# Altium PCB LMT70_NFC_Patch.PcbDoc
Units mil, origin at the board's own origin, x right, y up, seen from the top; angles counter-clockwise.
Board outline 1256 x 1256 mil, 2 copper layers (Top Layer, Bottom Layer); 28 components, 19 nets, 113 pads, 34 vias.
Unrouted connection lines stored in the file: 2.
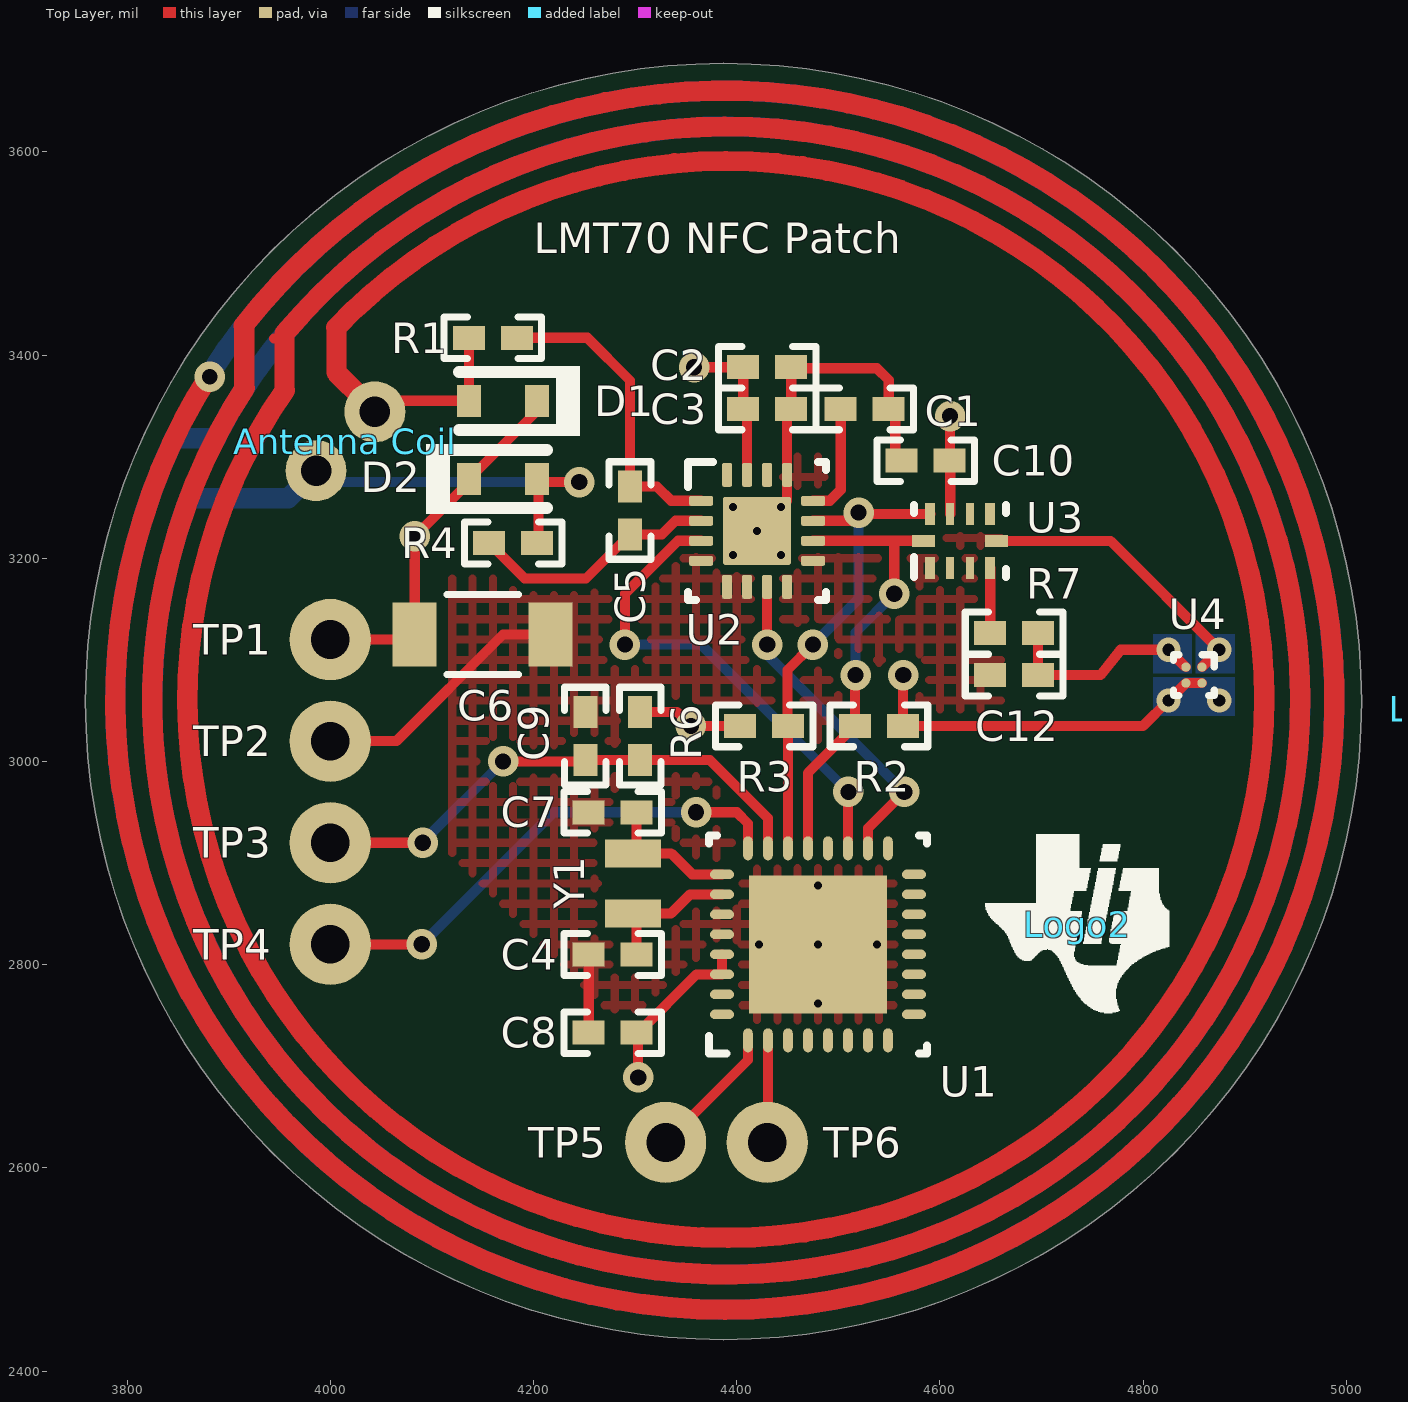
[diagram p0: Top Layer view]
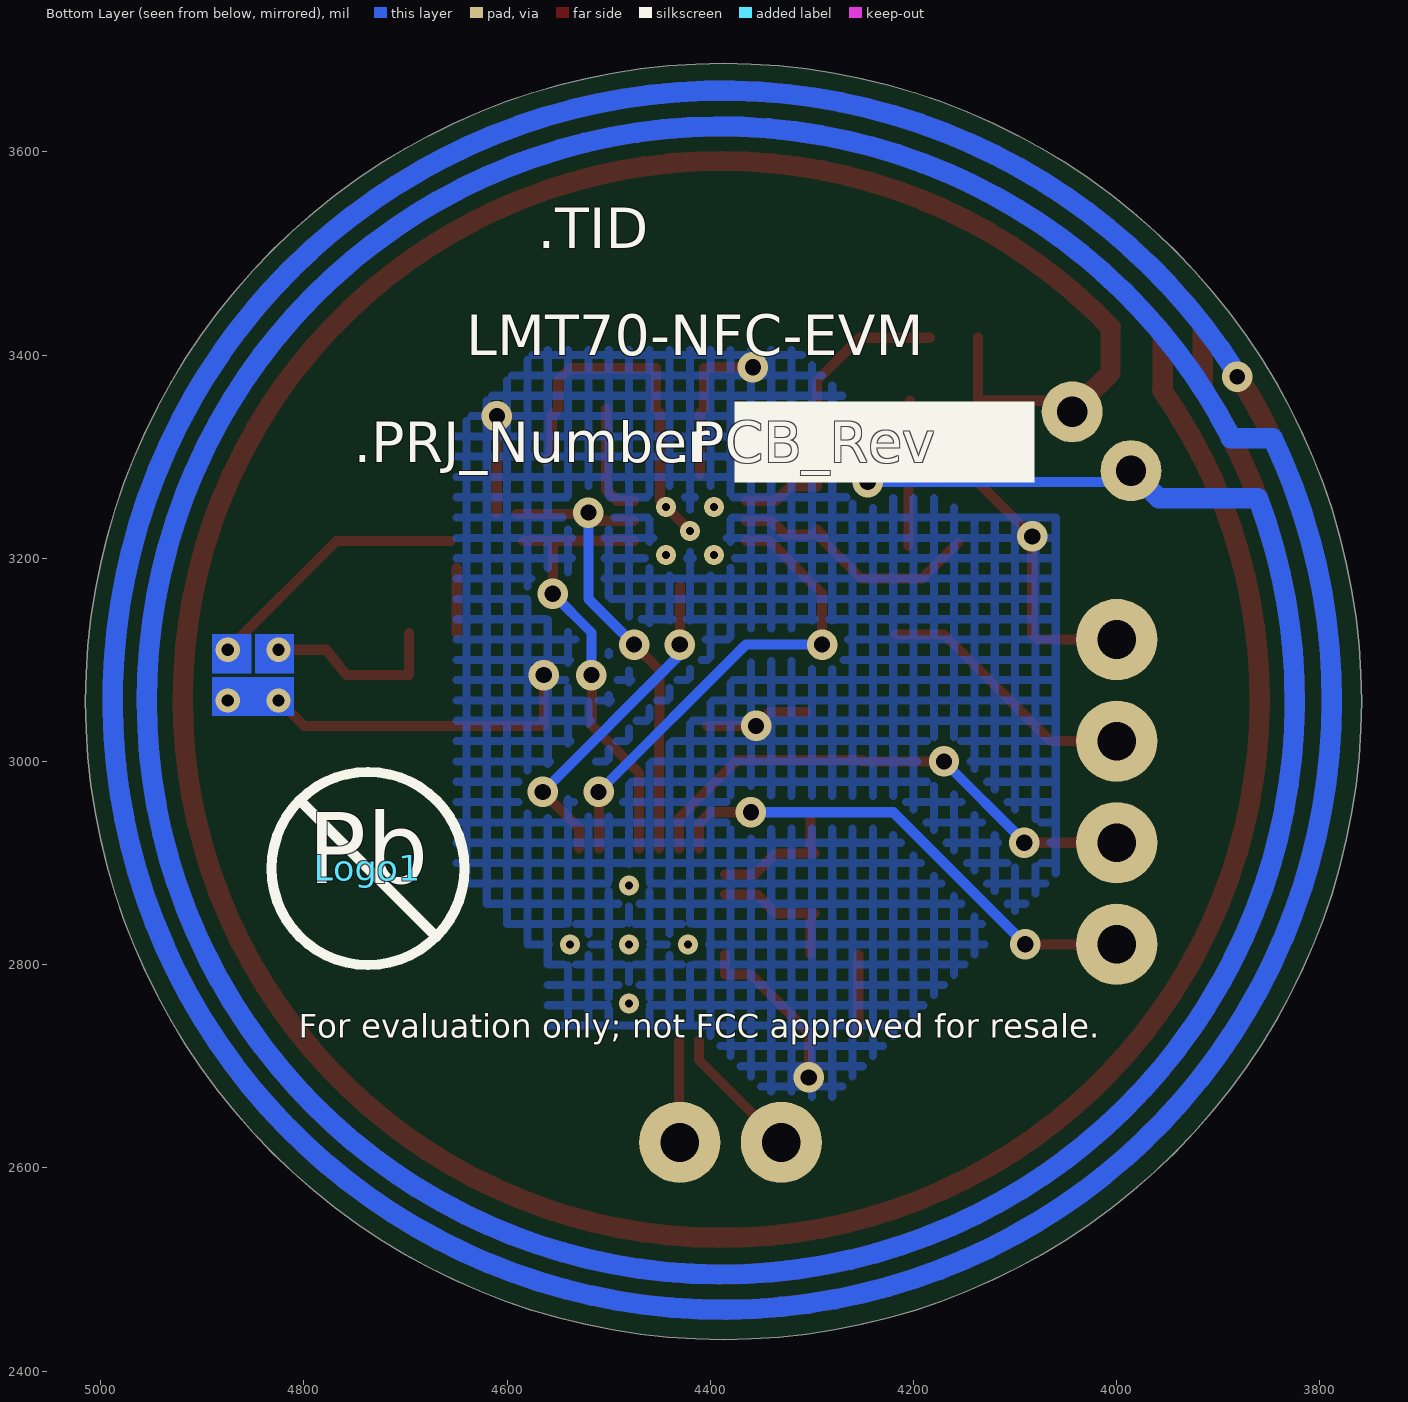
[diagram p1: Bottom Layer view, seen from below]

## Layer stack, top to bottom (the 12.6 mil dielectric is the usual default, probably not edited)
Top Solder: solder mask 0.4, Solder Resist, Dk 3.5
Top Layer: signal copper 1.4
Dielectric1: dielectric 12.6, FR-4, Dk 4.8
Bottom Layer: signal copper 1.4
Bottom Solder: solder mask 0.4, Solder Resist, Dk 3.5

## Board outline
3759.02,3059 ccw(c4387.02,3059) 4387.02,2431 ccw(c4387.02,3059) 5015.02,3059 ccw(c4387.02,3059) 4387.02,3687 ccw(c4387.02,3059)

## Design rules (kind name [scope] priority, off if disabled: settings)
AcuteAngle [All] p1: minimum=4.50000000000000E+0001 checktracksonly=FALSE
AssemblyTestPointUsage [All] p1: valid=2
Clearance Clearance_BoardEdge_MountingHoles [OnCopper and InComponentClass('Mounting Holes') vs IsKeepOut] p1: gap=20
Clearance Clearance_BoardEdge_Poly [OnCopper and InPoly vs IsKeepOut] p2: gap=20
Clearance Clearance_BoardEdge [OnCopper and Not InComponentClass('Logo') and not InComponentClass('FiducialMark') and not InRegion(1000,500,4000,800) vs IsKeepOut] p3: gap=20
Clearance Clearance_Poly [InPolygon] p4: gap=7
Clearance [All] p5: gap=3
ComponentClearance ComponentClearance_Shunt [InComponentClass('Header') vs InComponentClass('Shunt')] p1 off: gap=0 collisioncheckmode=3 verticalgap=0 showdistances=FALSE
ComponentClearance ComponentClearance_Logo [InComponentClass(Logo)] p2 off: gap=50 collisioncheckmode=3 verticalgap=10 showdistances=FALSE
ComponentClearance ComponentClearance_ScrewToNut [(HasFootprint('NY PMS 440 0025 PH')) vs (HasFootprint('Keystone_1902C'))] p3 off: gap=5 collisioncheckmode=3 verticalgap=10 showdistances=FALSE
ComponentClearance ComponentClearance_MountingHoles [InComponentClass('Mounting Holes')] p4 off: gap=250 collisioncheckmode=3 verticalgap=100000 showdistances=FALSE
ComponentClearance ComponentClearance_SmallPassives [HasFootprint('0201*') or HasFootprint('0402*') or HasFootprint('0508') or HasFootprint('0603*') or HasFootprint('0612') or HasFootprint('0805*') or HasFootprint('0815*') or HasFootprint('0830*') or HasFootprint('1206*') or HasFootprint('1210*') or HasFootprint('1808*') or HasFootprint('1812*') or HasFootprint('1825*') or HasFootprint('2010*') or HasFootprint('2220*') or HasFootprint('2225*') or HasFootprint('2512*') or HasFootprint('2728*') or HasFootprint('3518*') vs HasFootprint('0201*') or HasFootprint('0402*') or HasFootprint('0508') or HasFootprint('0603*') or HasFootprint('0612') or HasFootprint('0805*') or HasFootprint('0815*') or HasFootprint('0830*') or HasFootprint('1206*') or HasFootprint('1210*') or HasFootprint('1808*') or HasFootprint('1812*') or HasFootprint('1825*') or HasFootprint('2010*') or HasFootprint('2220*') or HasFootprint('2225*') or HasFootprint('2512*') or HasFootprint('2728*') or HasFootprint('3518*')] p5 off: gap=20 collisioncheckmode=3 verticalgap=10 showdistances=FALSE
ComponentClearance ComponentClearance_THtoSMT [IsThruComponent vs IsSMTComponent] p6 off: gap=100 collisioncheckmode=3 verticalgap=100000 showdistances=FALSE
ComponentClearance ComponentClearance_THtoTH [IsThruComponent vs IsThruComponent] p7 off: gap=118.11 collisioncheckmode=3 verticalgap=100000 showdistances=FALSE
ComponentClearance [All] p8 off: gap=4 collisioncheckmode=3 verticalgap=10 showdistances=FALSE
DiffPairsRouting [All] p1: maxlimit=100 minlimit=10 mostfreqgap=10 toplayer_minwidth=15 toplayer_maxwidth=15 toplayer_prefwidth=15 bottomlayer_minwidth=15 bottomlayer_maxwidth=15 bottomlayer_prefwidth=15 maxuncoupledlength=1000
FabricationTestPointUsage TestPointUsage [All] p1: valid=2 allowmultiple=FALSE
FabricationTestpoint Testpoint [All] p1: side=3 testpointundercomponent=TRUE minsize=40 maxsize=100 preferedsize=60 minholesize=0 maxholesize=40 preferedholesize=32 testpointgrid=1 allowsidetop=TRUE allowsidebottom=TRUE usegrid=TRUE gridtolerance=0.01
FanoutControl Fanout_LCC [IsLCC] p1: bgadir=Out bgaviamode=Centered fanoutstyle=Auto fanoutdirection=Alternating viagrid=1 // Fanout_LCC (Default Rule)
FanoutControl Fanout_BGA [IsBGA] p2: bgadir=Out bgaviamode=Centered fanoutstyle=Auto fanoutdirection=Alternating viagrid=1 // Fanout_BGA (Default Rule)
FanoutControl Fanout_Default [All] p4: bgadir=Out bgaviamode=Centered fanoutstyle=Auto fanoutdirection=Alternating viagrid=1 // Fanout_Default (Default Rule)
FanoutControl Fanout_Small [(CompPinCount < 5)] p5: bgadir=Out bgaviamode=Centered fanoutstyle=Auto fanoutdirection=OutThenIn viagrid=1 // Fanout_Small (Default Rule)
HoleSize [All] p1: absolutevalues=TRUE maxlimit=550 minlimit=5 maxpercent=80.000 minpercent=20.000
HoleToHoleClearance [All] p1: gap=3 allowstackedmicrovias=TRUE
MinimumAnnularRing MinimumAnnularRing_ThermalPadVias [IsVia and InAnyComponent] p1: minimumring=5.91
MinimumAnnularRing [All] p2: minimumring=5
MinimumSolderMaskSliver MinimumSolderMaskSliver_Logo [InComponentClass('Logo') vs InComponentClass('Logo')] p1: minsoldermaskwidth=0.7
MinimumSolderMaskSliver [All] p2: minsoldermaskwidth=3
NetAntennae [All] p1 off: netantennaetolerance=0
PlaneConnect [All] p1: planeconnectstyle=Relief reliefexpansion=10 reliefentries=4 reliefconductorwidth=10 reliefairgap=10
PolygonConnect [All] p1: connectstyle=Direct reliefconductorwidth=10 reliefentries=4 polygonreliefangle="90 Angle" airgapwidth=10
RoutingVias ThermalPadVias [IsVia and InAnyComponent] p1: holewidth=7.87 width=19.68 viastyle="Through Hole" minholewidth=7.87 minwidth=19.68 maxholewidth=15 maxwidth=30
RoutingVias [All] p2: holewidth=12 width=28 viastyle="Through Hole" minholewidth=5 minwidth=20 maxholewidth=100 maxwidth=150
SilkToSilkClearance [All] p1: silktosilkclearance=2
SilkToSolderMaskClearance SilkscreenOverComponentPads [IsPad] p1: minsilkscreentomaskgap=2.6 clearancetoexposedcopper=TRUE
SolderMaskExpansion [All] p1: expansion=3
UnpouredPolygon [All] p1: allowunpoured=FALSE
Width [All] p1: maxlimit=100 minlimit=6 preferedwidth=10 checkconnectedcopper=TRUE
13 further rules are at their usual default settings.

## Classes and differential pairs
component class Logo: Logo2

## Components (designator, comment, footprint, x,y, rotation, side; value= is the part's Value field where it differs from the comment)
"Antenna Coil" "Antenna Coil" PCBComponent_1 4389,3060 r315 top locked
C1 "GRM155R61C474KE01" 0402 4526,3347 r0 top
C2 "GRM155R61E105KA12D" 0402 4430,3388 r0 top
C3 "GRM155R61E104KA87D" 0402 4430,3347 r0 top
C4 "GRM1555C1E120JA01D" 0402 4278,2810 r0 top
C5 "GRM1555C1E390JA01D" 0402 4295,3247 r270 top
C6 "C3216X5R1A107M160AC" 1206_190 4150,3125 r0 top
C7 "GRM1555C1E120JA01D" 0402 4278,2950 r0 top
C8 "GRM155R61E104KA87D" 0402 4278,2733 r180 top
C9 "GRM155R71C222KA01D" 0402 4251,3025 r90 top
C10 "GRM155R61E104KA87D" 0402 4586,3296 r180 top
C12 "GRM155R61E102KA01D" 0402 4673,3085 r180 top
D1 "CDBU0130L" SOD-523F 4170,3355 r180 top
D2 "CDBU0130L" SOD-523F 4170,3278 r0 top
Logo1 "Pb-Free Symbol" Pb-Free_Overlay_Medium 4736.94,2894.7 r180 bottom
Logo2 "Texas Instruments" TI_Symbol_Overlay_Small 4735,2840 r0 top
Logo3 "FCC disclaimer" FCC_disclaimer 5095,3052 r90 top
R1 "CRCW04020000Z0ED" 0402 4160,3417 r180 top
R2 "CRCW04024K70JNED" 0402 4540,3035 r0 top
R3 "CRCW04024K70JNED" 0402 4427,3035 r180 top
R4 "CRCW04020000Z0ED" 0402 4180,3215 r0 top
R6 "CRCW040233K0JNED" 0402 4305,3025 r90 top
R7 "CRCW04020000Z0ED" 0402 4673,3126.42 r0 top
U1 "MSP430G2403IRHB32R" RHB0032E 4480,2820 r90 top
U2 "RF430CL330HIRGTR" RGT0016C 4420,3227 r0 top
U3 "ADS1113IRUGR" RUG0010A 4620,3217 r90 top
U4 "LMT70YFQR" YFQ0004ACAC 4850,3085 r270 top
Y1 "FC-12M 32.7680KA-A3" Epson_FC-12M 4297.76,2880 r270 top

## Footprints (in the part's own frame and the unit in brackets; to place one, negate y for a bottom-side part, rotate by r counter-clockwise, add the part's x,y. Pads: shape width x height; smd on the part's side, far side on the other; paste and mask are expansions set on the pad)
0402 [mm] "0402 from SM-752 data"
  rect 0.8x0.6 smd: 1(-0.6,0) 2(0.6,0)
  silkscreen extent -1.22,-0.52 1.22,0.52, body extent -0.55,-0.3 0.55,0.3, height 0.6
1206_190 [mm] "1206_190"
  rect 1.1x1.6 smd: 1(-1.7,0) 2(1.7,0)
  silkscreen extent -0.9,-1 0.9,1, body extent -1.75,-0.95 1.75,0.95, height 1.9
Epson_FC-12M [mm] "Epson"
  rect 0.7x1.4 smd: 1(-0.75,0) 2(0.75,0)
  body extent -1.05,-0.63 1.05,0.63, height 0.6
FCC_disclaimer [mil]
Pb-Free_Overlay_Medium [mil]
  silkscreen extent -95,-95 95,95
PCBComponent_1 [mil]
  round 60 hole 30: 1(-445,-43.17) 2(-445,-125)
  Top Layer lines w15: -452.3,-50.46 -460.26,-42.5
  Top Layer lines w20: -586.28,-131.22 ccw(c-0.75,-0.24) -596.14,-74.45 ; -552.64,-117.36 -595.62,-74.38 ; -552.1,-117.24 ccw(c0.5,0.5) -562.13,-51.23 ; -523.17,-90.83 -562.45,-51.55 ; -522.57,-90.73 ccw(c-0.55,0.93) -530.41,-11.29 ; -530.21,-11.29 -499,-42.5 -460.26,-42.5
  Bottom Layer lines w20: -566.17,-201 ccw(c-0.74,-0.28) -587.15,-127.22 ; -565.92,-200.92 -537,-172 ; -537.48,-172.15 cw(c0.49,0.54) -514.14,-232.66 -445,-163.52 -445,-125
RGT0016C [mm] "QFN, 16-Leads, Body 3x3mm, Pitch 0.5mm, Thermal Pad 1.7x1.7mm, TI Recommended"
  rrect40% 0.6x0.25 smd: 1(-1.4,0.75) 2(-1.4,0.25) 3(-1.4,-0.25) 4(-1.4,-0.75) 9(1.4,-0.75) 10(1.4,-0.25) 11(1.4,0.25) 12(1.4,0.75)
  rrect40% 0.25x0.6 smd: 5(-0.75,-1.4) 6(-0.25,-1.4) 7(0.25,-1.4) 8(0.75,-1.4) 13(0.75,1.4) 14(0.25,1.4) 15(-0.25,1.4) 16(-0.75,1.4)
  rrect6% 1.55x1.55 on Top Paste: 17(0,0)
  rrect6% 1.7x1.7 smd paste-0.85: 17(0,0)
  silkscreen extent -1.72,-1.73 1.72,1.73, body extent -1.57,-1.57 1.58,1.58, height 1.01
RHB0032E [mm] "QFN, 32-Leads, Body 5x5mm, Pitch 0.5mm, Thermal Pad 3.45x3.45mm, TI Recommended"
  oval 0.6x0.24 smd: 1(-2.4,1.75) 2(-2.4,1.25) 3(-2.4,0.75) 4(-2.4,0.25) 5(-2.4,-0.25) 6(-2.4,-0.75) 7(-2.4,-1.25) 8(-2.4,-1.75) 17(2.4,-1.75) 18(2.4,-1.25) 19(2.4,-0.75) 20(2.4,-0.25) 21(2.4,0.25) 22(2.4,0.75) 23(2.4,1.25) 24(2.4,1.75)
  oval 0.24x0.6 smd: 9(-1.75,-2.4) 10(-1.25,-2.4) 11(-0.75,-2.4) 12(-0.25,-2.4) 13(0.25,-2.4) 14(0.75,-2.4) 15(1.25,-2.4) 16(1.75,-2.4) 25(1.75,2.4) 26(1.25,2.4) 27(0.75,2.4) 28(0.25,2.4) 29(-0.25,2.4) 30(-0.75,2.4) 31(-1.25,2.4) 32(-1.75,2.4)
  rect 3.45x3.45 smd paste-1.725: 33(0,0)
  silkscreen extent -2.72,-2.73 2.72,2.73, body extent -2.57,-2.57 2.58,2.58, height 1.01
RUG0010A [mm] "QFN, 10-Leads, Body 2x1.5mm. Pitch 0.5mm, TI Recommended"
  rect 0.55x0.25 smd: 1(-0.675,0.75) 4(-0.675,-0.75) 6(0.675,-0.75) 9(0.675,0.75)
  rect 0.55x0.2 smd: 2(-0.675,0.25) 3(-0.675,-0.25) 7(0.675,-0.25) 8(0.675,0.25)
  rect 0.3x0.575 smd: 5(0,-0.913) 10(0,0.913)
  silkscreen extent -0.9,-1.15 0.9,1.15, body extent -0.77,-1.02 0.77,1.02, height 0.41
SOD-523F [mm] "COMCHIP"
  rect 0.6x0.8 smd paste-0.05: 1(-0.85,0) 2(0.85,0)
  silkscreen extent -1.92,-0.88 1.1,0.87, body extent -0.9,-0.5 0.9,0.5, height 0.85
TI_Symbol_Overlay_Small [mil]
  silkscreen extent -90,-88 91,88
YFQ0004ACAC [mm] "WCSP, 4-Leads, Body 0.84x0.84mm, Pitch 0.4mm"
  round 0.23 smd paste-0.13 mask+0.038: A1(-0.2,0.2) A2(0.2,0.2) B1(-0.2,-0.2) B2(0.2,-0.2)
  silkscreen extent -0.51,-0.51 0.51,0.51, body extent -0.42,-0.42 0.42,0.42, height 0.58

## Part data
"Antenna Coil": library part Component_1
C1: "CAP, CERM, 0.47 µF, 16 V, +/- 10%, X5R, 0402"
C2: "CAP, CERM, 1 µF, 25 V, +/- 10%, X5R, 0402"
C3 C8 C10: "CAP, CERM, 0.1 µF, 25 V, +/- 10%, X5R, 0402"
C4 C7: "CAP, CERM, 12 pF, 25 V, +/- 5%, C0G/NP0, 0402"
C5: "CAP, CERM, 39 pF, 25 V, +/- 5%, C0G/NP0, 0402"
C6: "CAP, CERM, 100 µF, 10 V, +/- 20%, X5R, 1206_190"
C9: "CAP, CERM, 2200 pF, 16 V, +/- 10%, X7R, 0402"
C12: "CAP, CERM, 1000 pF, 25 V, +/- 10%, X5R, 0402"
D1 D2: "Diode, Schottky, 35 V, 0.1 A, SOD-523F"
Logo1: library part Pb-Free
Logo2: library part TI_Logo, "Texas Instrument Corporate Signature"
Logo3: library part FCC_disclaimer, "FCC_disclaimer"
R1 R4 R7: "RES, 0, 5%, 0.063 W, 0402"
R2 R3: "RES, 4.7 k, 5%, 0.063 W, 0402"
R6: "RES, 33 k, 5%, 0.063 W, 0402"
U1: "16 MHz Mixed Signal Microcontroller with 8 KB Flash, 512 B SRAM and 24 GPIOs, -40 to 85 degC, 32-pin QFN (RHB), Green (RoHS & no Sb/Br)"
U2: "DYNAMIC NFC INTERFACE TRANSPONDER, RGT0016C"
U3: "Ultra-Small, Low-Power, 16-Bit Analog-to-Digital Converter with Internal Reference, DGS0010A"
U4: "±0.1°C Precision Analog Temperature Sensor, RTD and Precision NTC Thermistor IC, YFQ0004ACAC"
Y1: "Crystal, 32.768kHz, 12.5pF, SMD"

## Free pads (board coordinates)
  round 80 hole 37.99: 0(4000,2820) 0(4000,2920) 0(4000,3020) 0(4000,3120) 0(4330,2625) 0(4430,2625)

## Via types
v1: diameter 30, hole 16, Top Layer to Bottom Layer, tented both sides, 15 vias
v2: diameter 19.68, hole 7.87, Top Layer to Bottom Layer, tented top, 5 vias
v3: diameter 19.68, hole 7.87, Top Layer to Bottom Layer, 5 vias
v4: diameter 24, hole 12, Top Layer to Bottom Layer, 4 vias
v5: diameter 30, hole 16, Top Layer to Bottom Layer, 4 vias
v6: diameter 30, hole 15, Top Layer to Bottom Layer, 1 vias

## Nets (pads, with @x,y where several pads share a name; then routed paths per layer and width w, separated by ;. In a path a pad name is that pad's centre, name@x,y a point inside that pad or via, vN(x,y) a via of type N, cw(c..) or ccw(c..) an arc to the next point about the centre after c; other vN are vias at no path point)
ANT1: "Antenna Coil.1" D1.2 R1.2 | length 168.2
  Top Layer w10: 3944.64,3416.16 3953.53,3416.16 ; 4043.81,3344.14 4054.68,3355 D1.2 4136.54,3416.84 R1.2
  other v6: 3881.3,3378.59
ANT2: "Antenna Coil.2" D2.2 R4.2 | length 365.6
  Top Layer w10: D2.2 4206.46,3275 v1(4245,3275) ; R4.2@4205,3212.16 D2.2@4205,3275
  Bottom Layer w10: 3985,3275 v1(4245,3275)
GND: C1.2 C2.2 C3.2 C4.1 C6.2 C7.1 C8.2 C9.2 C10.2 C12.2 pad.0@4000,3020 U1.27 U1.28 U1.33 U2.4 U2.5 U2.6 U2.8 U2.9 U2.13 U3.1 U3.3 U3.5 U4.A1 | length 984.4
  Top Layer w10: pad.0@4000,3020 4065,3020 4170,3125 C6.2 ; C8.2 4254.38,2790 C4.1 ; 4420,3227 4449.53,3256.53 U2.13 4449.53,3342.9 C3.2 4453.62,3387 4538,3387 4549.62,3375.38 C1.2 4556,3340.62 4556,3302.38 C10.2 ; U3.5 4768,3217 v4(4875,3110) U4.A1
  other v3: 4480,2761.93 4421.93,2820 4480,2820 4538.07,2820 4480,2878.07
LMT70_TAO: C12.1 R7.2 U4.B1 | length 206
  Top Layer w10: R7.2 C12.1 4758,3085 4778,3110 v4(4825,3110) U4.B1
NetC1_1: C1.1 U2.12 | length 111.4
  Top Layer w10: U2.12 4491.53,3256.53 4502.38,3267.38 C1.1
NetC4_2: C4.2 U1.26 Y1.2 | length 137.5
  Top Layer w10: C4.2@4301.38,2810 4301.38,2846.85 Y1.2 4335.47,2850.47 4354.21,2869.21 U1.26
NetC5_1: C5.1 R1.1 U2.1 | length 308.9
  Top Layer w10: R1.1 4253,3417 4295,3375 C5.1 4321.38,3270.62 4335.47,3256.53 U2.1
NetC5_2: C5.2 R4.1 U2.2 | length 255.6
  Top Layer w10: R4.1 4191.38,3180 4251.62,3180 C5.2 4326.38,3223.38 4339.84,3236.84 U2.2 ; C5.2@4288.62,3222 C5.2@4295,3228.38
NetC7_2: C7.2 U1.25 Y1.1 | length 138.3
  Top Layer w10: C7.2@4301.38,2950 4301.38,2913.15 Y1.1 4335.47,2909.53 4356.1,2888.9 U1.25
NetR7_1: R7.1 U3.4 | length 64.1
  Top Layer w10: R7.1 4649.53,3126.57 U3.4
RF430_IRQ: U1.18 U2.7 | length 333.2
  Top Layer w10: U2.7 4429.84,3115.16 v5(4430,3115) ; U1.18 4529.21,2934.21 v1(4565,2970) v1@4560,2970
  Bottom Layer w10: v5(4430,3115) 4430,3105 v1(4565,2970)
RF430_RST: U1.19 U2.3 | length 482.3
  Top Layer w10: v5(4290,3115) 4290,3165 4342.16,3217.16 U2.3 ; U1.19 4509.53,2969.53 v1(4510,2970)
  Bottom Layer w10: v5(4290,3115) 4365,3115 v1(4510,2970)
SBWTCK: pad.0@4000,2820 U1.24 | length 494
  Top Layer w10: pad.0@4000,2820 v1(4090,2820) ; v1(4360,2950) 4400,2950 4411.1,2938.9 U1.24
  Bottom Layer w10: v1(4090,2820) 4220,2950 v1(4360,2950)
SBWTDIO: C9.1 pad.0@4000,2920 R6.1 U1.23 | length 518.5
  Top Layer w10: pad.0@4000,2920 v1(4091,2920) ; v1(4170,3000) 4249.62,3000 C9.1 R6.1 4373.62,3001.38 4430.79,2944.21 U1.23
  Bottom Layer w10: v1(4091,2920) 4091,2921 v1(4170,3000)
SCL: R2.1 U1.21 U2.10 U3.10 | length 446.8
  Top Layer w10: U1.21 4470.16,2988.78 R2.1 4516.38,3084.38 v5(4517,3085) ; U2.10 4555,3217.16 ; v1(4555,3165) 4555,3217.16 ; U3.10 4583.92,3217.16 4555,3217.16
  Bottom Layer w10: v5(4517,3085) 4517,3127 v1(4555,3165)
SDA: R3.1 U1.22 U2.11 U3.9 | length 484.1
  Top Layer w10: U1.22 4450.47,3034.85 R3.1 4450,3035.62 4450,3090 v5(4475,3115) ; U2.11 4511.84,3236.84 v1(4520,3245) 4521.43,3243.57 U3.9
  Bottom Layer w10: v5@4480,3115 v5(4475,3115) 4520,3160 v1(4520,3245)
UART_RX: pad.0@4330,2625 U1.1 | length 134.1
  Top Layer w10: pad.0@4330,2625 4411.1,2706.1 U1.1
UART_TX: pad.0@4430,2625 U1.2 | length 100.8
  Top Layer w10: pad.0@4430,2625 4430.79,2625.79 U1.2
VCC: C2.1 C3.1 C6.1 C8.1 C10.1 D1.1 D2.1 pad.0@4000,3120 R2.2 R3.2 R6.2 U1.29 U1.30 U2.15 U3.8 U4.A2 U4.B2 | length 1251.9
  Top Layer w10: pad.0@4000,3120 4078.07,3120 C6.1 v1(4083.07,3221.46) D2.1@4136.54,3274.93 ; D2.1 4203.46,3344.93 D1.1 ; v1(4303,2689) 4303,2731.62 C8.1 4303,2733 4360.47,2790.47 U1.30 U1.29 ; R6.2 4341.38,3048.62 v1(4355,3035) R3.2 ; v1(4358,3388) 4401.38,3388 4404.38,3385 4406.38,3387 C3.1 4410.16,3343.22 U2.15 ; v1@4563.62,3083.62 R2.2 4800,3035 v4(4825,3060) U4.B2 U4.A2 ; v1(4610,3340) 4610,3296.38 C10.1 4610.16,3295.46 U3.8
  other v1: 4564,3085
  other v4: 4875,3060
pads on no net: U1.3 U1.4 U1.5 U1.6 U1.7 U1.8 U1.9 U1.10 U1.11 U1.12 U1.13 U1.14 U1.15 U1.16 U1.17 U1.20 U1.31 U1.32 U2.14 U2.16 U2.17 U3.2 U3.6 U3.7
copper on no net:
  other v2: 4396.38,3203.38 4443.62,3203.38 4420,3227 4396.38,3250.62 4443.62,3250.62

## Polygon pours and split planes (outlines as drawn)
GND on Top Layer "Top Layer-No Net" (hatched 90Degree grid 20 track 8, remove dead copper, pour order 4): 4120,3180 4305,3180 4310,3180 4430,3300 4520,3300 4560,3260 4660,3260 4660,3180 4660,2930 4660,2740 4385,2740 4290,2740 4284.74,2745.26 4190,2840 4120,2910
VCC on Bottom Layer "Bottom Layer-No Net" (hatched 90Degree grid 20 track 8, remove dead copper, pour order 12): 4060,3240 4060,2950 4060,2890 4280,2670 4330,2670 4340,2670 4410,2740 4560,2740 4560,2800 4620,2860 4650,2890 4650,3325 4570,3405 4315,3405 4150,3240

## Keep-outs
Keep-Out Layer:
  text ".Layer_Name" at 1269,675.51 h60

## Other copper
Top Layer:
  pour cut-out: 4263.2,2888.75 4263.2,2871.25 4345.75,2871.25 4346,2871 4346,2889
  text ".Layer_Name" at 1269,675.51 h60
Bottom Layer:
  region net GND: 4852,3125 4852,3087 4890,3087 4890,3125
  region net LMT70_TAO: 4810,3125 4810,3087 4848,3087 4848,3125
  region net VCC: 4810,3083 4890,3083 4890,3045 4810,3045
  text ".Layer_Name" at 1269,675.51 h60

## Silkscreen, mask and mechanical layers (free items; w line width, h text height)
Top Overlay:
  text "LMT70 NFC Patch" at 4200,3500 h30
  text "TP1" at 3865,3105 h30
  text "TP2" at 3865,3005 h30
  text "TP3" at 3865,2905 h30
  text "TP4" at 3865,2805 h30
  text "TP5" at 4195,2610 h30
  text "TP6" at 4485,2610 h30
  text ".Layer_Name" at 1269,675.51 h60
Bottom Overlay:
  rectangle: 4081.07,3274.5 4376.07,3354.5
  text ".TID" at 4570,3505 h40
  text "LMT70-NFC-EVM" at 4640,3400 h40
  text ".PCB_Rev" at 4436.07,3294.5 h40
  text ".PRJ_Number" at 4751.07,3294.5 h40
  text ".Layer_Name" at 1269,675.51 h60
Top Paste:
  text ".Layer_Name" at 1269,675.51 h60
Bottom Paste:
  text ".Layer_Name" at 1269,675.51 h60
Top Solder:
  text ".Layer_Name" at 1269,675.51 h60
  text ".Layer_Name" at 1269,675.51 h60
Bottom Solder:
  text ".Layer_Name" at 1269,675.51 h60
Drill Guide:
  text ".Layer_Name" at 1269,675.51 h60
Mechanical 1:
  circle w10: c4387.02,3059 r628
  text ".Layer_Name" at 1269,675.51 h60
Mechanical 2:
  rectangle: 692,1259 817,1384
  rectangle: 817,1134 1192,1259
  lines w7: 692,1259 1692,1259 ; 692,1384 692,1134 1692,1134 1692,1384 ; 817,1134 817,1384 ; 942,1134 942,1384 ; 1192,1134 1192,1384 ; 1442,1134 1442,1384
  text ".Layer_Name" at 1269,675.51 h60
Mechanical 3:
  text ".Layer_Name" at 1269,675.51 h60
Mechanical 4:
  text ".Layer_Name" at 1269,675.51 h60
Mechanical 5:
  circle w3.94: c4243.57,3178.28 r11.81
  lines w3.94: 4208.14,3050.33 4208.14,3213.72 4371.52,3213.72 4371.52,3050.33 4208.14,3050.33
  lines w10: 400,603.83 7000,603.83 ; 400,807.17 7002,807.17 ; 400,1010.5 400,400.5 4405,400.5 7002,400.5 7002,1010.5 400.5,1010.5 400.5,400.5 1976,400.5 ; 2865,400.5 2865,1010.5 ; 4132,807.17 4132,1010.5 ; 4972,807.17 4972,1010.5 ; 5594,394 5594,596.83
  text ".Designator" at 4216.83,3112.02 h40
  text "COMPONENTS MARKED 'DNP' SHOULD NOT BE POPULATED." at 1845.5,1215.5 h60
  text "ASSEMBLY VARIANT:" at 1845,1100 h60
  text ".VariantName" at 2881,1100 h60
  text "PCB VIEWED FROM TOP SIDE" at 463.5,878.33 h60
  text "BOARD #:" at 2940,878.33 h60
  text ".PRJ_Number" at 3485.5,878.33 h60
  text "REV:" at 4330,878.33 h60
  text ".PCB_Rev" at 4621.5,878.33 h60
  text "SVN REV:" at 5168,878.33 h60
  text ".VersionControl_RevNumber" at 5674,878.33 h60
  text "TID #:" at 2940,675 h60
  text ".TID" at 3485.5,675 h60
  text "PLOT NAME =" at 463.5,469.66 h60
  text ".plot_File_Name" at 1269,469.66 h60
  text "GENERATED    :" at 2942,469.66 h60
  text ".Print_Date" at 3811.5,469.66 h60
  text ".Print_Time" at 4540.5,469.66 h60
  text "TEXAS INSTRUMENTS" at 5805,469.66 h60
Mechanical 6:
  lines w10: 399.5,806.67 7001.5,806.67 ; 401.5,603.33 7001.5,603.33 ; 1807.5,393.5 1807.5,596.33 ; 2429.5,806.67 2429.5,1010 ; 3269.5,806.67 3269.5,1010 ; 4536.5,400 4536.5,1010 ; 5425.5,400 7001,400 7001,1010 399.5,1010 399.5,400 2996.5,400 7001.5,400 7001.5,1010
  text "COMPONENTS MARKED 'DNP' SHOULD NOT BE POPULATED." at 6794,1216 h60
  text ".VariantName" at 5750,1100 h60
  text "ASSEMBLY VARIANT:" at 6789,1100 h60
  text ".VersionControl_RevNumber" at 1727.5,877.83 h60
  text "SVN REV:" at 2233.5,877.83 h60
  text ".PCB_Rev" at 2780,877.83 h60
  text "REV:" at 3071.5,877.83 h60
  text ".PRJ_Number" at 3916,877.83 h60
  text "BOARD #:" at 4461.5,877.83 h60
  text "PCB VIEWED FROM BOTTOM SIDE" at 6938,877.83 h60
  text ".TID" at 3916,674.5 h60
  text "TID #:" at 4461.5,674.5 h60
  text "TEXAS INSTRUMENTS" at 1596.5,469.16 h60
  text ".Print_Time" at 2861,469.16 h60
  text ".Print_Date" at 3590,469.16 h60
  text "GENERATED    :" at 4459.5,469.16 h60
  text ".plot_File_Name" at 6132.5,469.16 h60
  text "PLOT NAME =" at 6938,469.16 h60
Mechanical 9:
  drawing of 57 lines, arcs and shapes, not listed
  text "1" at 1431.84,9570.5 h70
  text "2" at 3927.5,9570.5 h70
  text "3" at 6416.84,9570.5 h70
  text "4" at 8923.51,9570.5 h70
  text "5" at 11422.5,9570.5 h70
  text "6" at 13927.5,9570.5 h70
  text "A" at 275.5,8427.5 h70
  text "A" at 15075.5,8427.5 h70
  text "B" at 275.5,6047.5 h70
  text "B" at 15075.5,6047.5 h70
  text "C" at 275.5,3672.5 h70
  text "C" at 15075.5,3672.5 h70
  text "PROJECT TITLE:" at 12035.5,1811.5 h45
  text ".PRJ_Title" at 12085.5,1678.17 h70
  text "DESIGNED FOR:" at 12035.5,1510.5 h45
  text ".PRJ_Customer" at 12085.5,1370.5 h70
  text "D" at 275.5,1302.5 h70
  text "D" at 15075.5,1302.5 h70
  text "FILE NAME:" at 12035.5,1210.5 h45
  text ".PCB_File_Name_No_Path" at 12085.5,1090.5 h70
  text "Texas Instruments (TI) and/or its licensors do not warrant the accuracy or completeness of this specification" at 7066,928.66 h45
  text "ENGINEER:" at 12035.5,920.5 h45
  text "LAYOUT BY:" at 13540.5,920.5 h45
  text "or any information contained therein. TI and/or its licensors do not warrant that this design will meet" at 7021.01,816 h45
  text ".PRJ_Engineer" at 12085.5,765.51 h70
  text ".PCB_Layout" at 13591,765.51 h70
  text "the specifications, will be suitable for your application or fit for any particular purpose, or will operate in" at 7021.01,703.33 h45
  text ".Layer_Name" at 1269,675.51 h60
  text "ALTIUM DESIGNER VERSION:" at 13540.5,610.5 h45
  text "an implementation. TI and/or its licensors do not warrant that the design is production worthy. You should" at 7021.01,590.67 h45
  text "completely validate and test your design implementation to confirm the system functionality for your application." at 7066,478 h45
  text ".print_Scale" at 12085.5,477.17 h70
  text ".Application_BuildNumber" at 13591,477.17 h70
  text "1" at 1431.84,270.5 h70
  text "2" at 3927.5,270.5 h70
  text "3" at 6416.84,270.5 h70
  text "4" at 8923.51,270.5 h70
  text "5" at 11422.5,270.5 h70
  text "6" at 13927.5,270.5 h70
Mechanical 10:
  drawing of 189 lines, arcs and shapes, not listed
  text "DESIGN INFORMATION" at 13073.02,7562 h60
  text "MIN. TRACK WIDTH:" at 12428.46,7382 h60
  text "8" at 13524.7,7382 h60
  text "MIL" at 13679.46,7382 h60
  text "MIN. CLEARANCE:" at 12428.46,7250 h60
  text "0.2" at 13464.7,7250 h60
  text "mm" at 13679.46,7250 h60
  text "MIN. VIA PAD SIZE:" at 12428.46,7118 h60
  text "24" at 13494.71,7118 h60
  text "MIL" at 13679.46,7118 h60
  text "0.05mm (2MIL)" at 13123.46,6976.29 h60
  text "MINIMUM ANNULAR RING" at 12099.23,6972 h60
  text "EXTERNAL" at 13831.46,6972 h60
  text "PER" at 12299.23,6854 h60
  text "IPC-D-275 CLASS 2 LEVEL C" at 12519.23,6854 h60
  text "MIL, HOLES" at 14007.46,6741.71 h60
  text "+/-" at 13615,6741 h60
  text "+/-" at 14469,6741 h60
  text "REGISTRATION TOLERANCES:" at 12099.23,6736 h60
  text "METAL" at 13299,6736 h60
  text "5" at 13875.2,6736 h60
  text "3" at 14708.2,6736 h60
  text "MIL" at 14824.46,6736 h60
  text "+/-" at 14469,6623 h60
  text "HOLE SIZE TOLERANCE (UNLESS OTHERWISE SPECIFIED):" at 12099.23,6618 h60
  text "3" at 14708.2,6618 h60
  text "MIL" at 14824.46,6618 h60
  text "MATERIAL:" at 12024.46,6408.54 h60
  text "FR-4 High Tg" at 13010.9,6268.21 h60
  text "FPC" at 14535,6265 h60
  text "FR-408" at 12445.46,6259.64 h60
  text "X" at 13755,6260 h60
  text "OTHER" at 13933.46,6259.64 h60
  text "62 MIL (1.6mm) +/-10%" at 12765.56,6096.92 h60
  text "THICKNESS:" at 12099.23,6092.64 h60
  text "X" at 12637.4,6092.64 h60
  text "OTHER" at 14050.46,6092.64 h60
  text "TOLERANCE:" at 12099.23,5934.64 h60
  text "X" at 12938.53,5934.64 h60
  text "ANSI IPC-6012 TYPE 3 CLASS 2" at 13125.48,5934.64 h60
  text "OTHER +/-" at 13125.46,5778.64 h60
  text "BOW & TWIST:" at 12099.23,5621.64 h60
  text "X" at 12938.53,5621.64 h60
  text "ANSI IPC-6012 TYPE 3 CLASS 2" at 13125.48,5621.64 h60
  text "OTHER +/-" at 13125.46,5463.13 h60
  text "DRILLING:" at 12024.46,5324.64 h60
  text "REFERENCE:" at 12099.23,5207.64 h60
  text "X" at 12747.46,5207.64 h60
  text "AS SHOWN" at 12934.46,5207.64 h60
  text "X" at 13648.46,5207.64 h60
  text "NC_DRILL FILES" at 13785.46,5207.64 h60
  text "PTH MIN COPPER THICKNESS:" at 12099.23,5049.64 h60
  text "X" at 13449.46,5049.64 h60
  text "1MIL" at 13586.46,5049.64 h60
  text "OTHER" at 14083.46,5049.64 h60
  text "BOARD FINISH:" at 12024.46,4890.64 h60
  text "SILKSCREEN:" at 12179.68,4772.64 h60
  text "X" at 13128.46,4772.64 h60
  text "TOP" at 13254.46,4772.64 h60
  text "X" at 13638.46,4772.64 h60
  text "BOTTOM" at 13765.46,4772.64 h60
  text "SILKSCREEN COLOR:" at 12179.68,4605.64 h60
  text "X" at 13127.42,4605.64 h60
  text "WHITE" at 13254.46,4605.64 h60
  text "OTHER" at 13765.46,4605.64 h60
  text "ORANGE" at 14493.46,4456.44 h60
  text "X" at 13850,4450 h60
  text "GREEN" at 13385.46,4446.44 h60
  text "OTHER" at 14003.46,4446.44 h60
  text "SOLDER RESIST COLOR:" at 12179.68,4435.64 h60
  text "X" at 13258.42,4276.44 h60
  text "MATTE" at 13385.46,4276.44 h60
  text "SEMI-GLOSS" at 14003,4275.8 h60
  text "IMMERSION GOLD (ENIG)" at 13085.46,4087.92 h60
  text "ENEPIG" at 14423,4084.64 h60
  text "SURFACE FINISH:" at 12024.46,4083.64 h60
  text "X" at 12898.51,4083.64 h60
  text "IMM. TIN/SILVER OR EQUIV" at 12354,3926.64 h60
  text "OTHER" at 13785.46,3926.64 h60
  text "ARRAY/PANEL:" at 12024.46,3747.64 h60
  text "CUT AND TRIM PER M1 BOARD OUTLINE" at 13085.46,3743.35 h60
  text "N.C. ROUTE" at 13085.46,3591.64 h60
  text "X" at 13764.46,3591.64 h60
  text "V. SCORE" at 13951.46,3591.64 h60
  text "CERTIFICATION:" at 12024.46,3454.64 h60
  text "MATERIALS AND WORKMANSHIP FOR ALL PCBS" at 12749.46,3454.64 h60
  text "TO MEET OR EXCEED THE REQUIREMENTS OF:" at 12749.46,3356.64 h60
  text "X" at 12375.96,3220.13 h60
  text "ANSI IPC-A-600F CLASS ->" at 12514.96,3220.13 h60
  text "X" at 14154.02,3220.13 h60
  text "2" at 14272.96,3220.14 h60
  text "1" at 13957.96,3218.64 h60
  text "3" at 14626.96,3218.64 h60
  text "X" at 12378.02,3060.64 h60
  text "UL 94V-0" at 12514.96,3060.64 h60
  text "X" at 13190.02,3060.64 h60
  text "RoHS" at 13326.96,3060.64 h60
  text "OTHER" at 13971.36,3060.64 h60
  text "PER ORDER" at 14368.42,3060.64 h60
  text "ADDITIONAL REQUIREMENTS:" at 12024.46,2919.64 h60
  text "MICROSECTION:" at 12099.23,2804.64 h60
  text "YES" at 13004.96,2804.64 h60
  text "REQUIRED" at 13866.46,2648.49 h60
  text "BARE BOARD ELEC. TEST:" at 12099.23,2645.64 h60
  text "NONE" at 13404.96,2645.64 h60
  text "X" at 13739.46,2645.64 h60
  text "PER ORDER" at 14458.46,2645.64 h60
  text "MANUFACTURER'S UL:" at 12099.23,2488.64 h60
  text "RAIL" at 13264.96,2484.35 h60
  text "METAL" at 13756.77,2484.35 h60
  text "X" at 14132,2484 h60
  text "SILK" at 14268.46,2484.35 h60
  text ".Layer_Name" at 1269,675.51 h60
Mechanical 11:
  lines w10: 400,603.83 7000,603.83 ; 400,807.17 7002,807.17 ; 400,1010.5 400,400.5 4405,400.5 7002,400.5 7002,1010.5 400.5,1010.5 400.5,400.5 1976,400.5 ; 2865,400.5 2865,1010.5 ; 4132,807.17 4132,1010.5 ; 4972,807.17 4972,1010.5 ; 5594,394 5594,596.83
  text "ALL ARTWORK VIEWED FROM TOP SIDE" at 463.5,878.33 h60
  text "BOARD #:" at 2940,878.33 h60
  text ".PRJ_Number" at 3485.5,878.33 h60
  text "REV:" at 4330,878.33 h60
  text ".PCB_Rev" at 4621.5,878.33 h60
  text "SVN REV:" at 5168,878.33 h60
  text ".VersionControl_RevNumber" at 5674,878.33 h60
  text "LAYER NAME =" at 463.5,675.51 h60
  text "TID #:" at 2940,675 h60
  text ".TID" at 3485.5,675 h60
  text "PLOT NAME =" at 463.5,469.66 h60
  text ".plot_File_Name" at 1269,469.66 h60
  text "GENERATED    :" at 2942,469.66 h60
  text ".Print_Date" at 3811.5,469.66 h60
  text ".Print_Time" at 4540.5,469.66 h60
  text "TEXAS INSTRUMENTS" at 5805,469.66 h60
Mechanical 12:
  drawing of 191 lines, arcs and shapes, not listed
  text "Layer" at 10482.34,9364 h60
  text "Name" at 10892.26,9364 h60
  text "Material" at 11822,9364 h60
  text "Thickness" at 12681.77,9364 h60
  text "Constant" at 13331.6,9364 h60
  text "Board Layer Stack" at 13901.46,9364 h60
  text "1" at 10482.34,9244 h60
  text "Top Overlay" at 10892.26,9244 h60
  text "2" at 10482.34,9124 h60
  text "Top Solder" at 10892.26,9124 h60
  text "Solder Resist" at 11822,9124 h60
  text "0.40mil" at 12681.77,9124 h60
  text "3.5" at 13331.6,9124 h60
  text "3" at 10482.34,9004 h60
  text "Top Layer" at 10892.26,9004 h60
  text "Copper" at 11822,9004 h60
  text "1.40mil" at 12681.77,9004 h60
  text "4" at 10482.34,8884 h60
  text "Dielectric1" at 10892.26,8884 h60
  text "FR-4" at 11822,8884 h60
  text "59.20mil" at 12681.77,8884 h60
  text "4.8" at 13331.6,8884 h60
  text "5" at 10482.34,8764 h60
  text "Bottom Layer" at 10892.26,8764 h60
  text "Copper" at 11822,8764 h60
  text "1.40mil" at 12681.77,8764 h60
  text "6" at 10482.34,8644 h60
  text "Bottom Solder" at 10892.26,8644 h60
  text "Solder Resist" at 11822,8644 h60
  text "0.40mil" at 12681.77,8644 h60
  text "3.5" at 13331.6,8644 h60
  text "7" at 10482.34,8524 h60
  text "Bottom Overlay" at 10892.26,8524 h60
  text ".Layer_Name" at 1269,675.51 h60
Mechanical 13:
  text ".Layer_Name" at 1269,675.51 h60
Mechanical 14:
  text ".Layer_Name" at 1269,675.51 h60
Mechanical 15:
  text ".Layer_Name" at 1269,675.51 h60
Mechanical 16:
  text ".Layer_Name" at 1269,675.51 h60
Drill Drawing:
  circle w1: c6402.73,3777.35 r24.89
  lines w1: 6377.84,3304.45 6402.73,3316.9 6427.62,3304.45 6415.17,3329.34 6427.62,3354.23 6402.73,3341.79 6377.84,3354.23 6390.28,3329.34 6377.84,3304.45 ; 6377.84,3466.23 6390.28,3466.23 6402.73,3453.79 6415.17,3466.23 6427.62,3466.23 6415.17,3478.68 6427.62,3491.12 6415.17,3491.12 6402.73,3503.57 6390.28,3491.12 6377.84,3491.12 6390.28,3478.68 6377.84,3466.23 ; 6377.84,3603.12 6427.62,3603.12 6427.62,3652.9 6377.84,3652.9 6377.84,3603.12 ; 6377.84,3951.57 6427.62,3951.57 6402.73,3901.8 6377.84,3951.57 ; 6377.84,4063.57 6390.28,4063.57 6390.28,4051.13 6415.17,4051.13 6415.17,4063.57 6427.62,4063.57 6427.62,4088.46 6415.17,4088.46 6415.17,4100.91 6390.28,4100.91 6390.28,4088.46 6377.84,4088.46 6377.84,4063.57
  lines w12: 6310,3259.65 8426.94,3259.65 ; 6310,4155.66 8426.94,4155.66 ; 6680.25,3110.32 6680.25,4305 ; 7037.06,3110.32 7037.06,4305 ; 7698.16,3110.32 7698.16,4305 ; 7982.16,3110.32 7982.16,4305 ; 6310,3110.32 8426.94,3110.32 8426.94,4305 6310,4305 6310,3110.32
  text "Symbol" at 6399.6,4200.47 h72
  text "Quantity" at 6725.05,4200.47 h72
  text "Finished Hole Size" at 7081.86,4200.47 h72
  text "Plated" at 7742.96,4200.47 h72
  text "Hole Type" at 8026.96,4200.47 h72
  text "10" at 6725.05,4051.13 h60
  text "7.87mil (0.200mm)" at 7081.86,4051.13 h60
  text "PTH" at 7742.96,4051.13 h60
  text "Round" at 8026.96,4051.13 h60
  text "4" at 6725.05,3901.8 h60
  text "12.00mil (0.305mm)" at 7081.86,3901.8 h60
  text "PTH" at 7742.96,3901.8 h60
  text "Round" at 8026.96,3901.8 h60
  text "1" at 6725.05,3752.46 h60
  text "15.00mil (0.381mm)" at 7081.86,3752.46 h60
  text "PTH" at 7742.96,3752.46 h60
  text "Round" at 8026.96,3752.46 h60
  text "19" at 6725.05,3603.12 h60
  text "16.00mil (0.406mm)" at 7081.86,3603.12 h60
  text "PTH" at 7742.96,3603.12 h60
  text "Round" at 8026.96,3603.12 h60
  text "2" at 6725.05,3453.79 h60
  text "30.00mil (0.762mm)" at 7081.86,3453.79 h60
  text "PTH" at 7742.96,3453.79 h60
  text "Round" at 8026.96,3453.79 h60
  text "6" at 6725.05,3304.45 h60
  text "37.99mil (0.965mm)" at 7081.86,3304.45 h60
  text "PTH" at 7742.96,3304.45 h60
  text "Round" at 8026.96,3304.45 h60
  text "42 Total" at 6725.05,3155.12 h60
  text ".Layer_Name" at 1269,675.51 h60

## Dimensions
692,1134 to 1692,1134 on Mechanical 2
